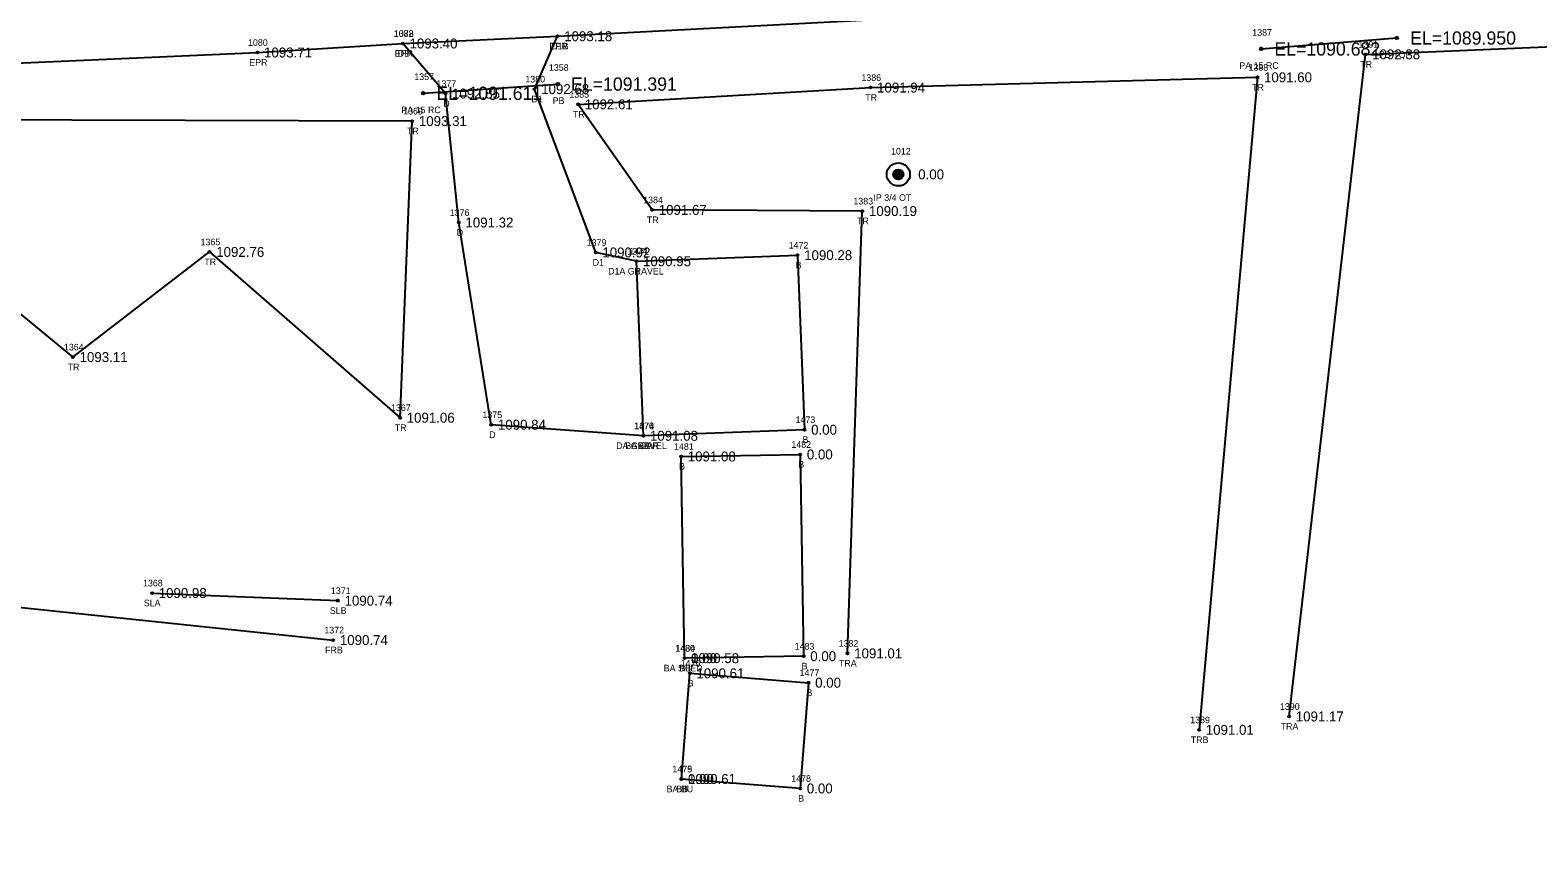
# Model space of a CAD drawing. Extents: x 1539151 to 1541799, y 1198646 to 1201165.
# Drawn here: x 1539723.1 to 1539950.8, y 1199238.5 to 1199362.5 of the extents above; entities that cross this region are included whole.
import ezdxf

# ---------------------------------------------------------------- set-up
doc = ezdxf.new("R2010")
doc.units = 0
for name, color, linetype in [('RD_EX_Bldg', 7, 'Continuous'), ('RD_EX_Bldg_txCode', 7, 'Continuous'), ('RD_EX_DR_Pipe', 7, 'Continuous'), ('RD_EX_DR_Pipe_txCode', 7, 'Continuous'), ('RD_EX_Driveway', 7, 'Continuous'), ('RD_EX_Driveway_txCode', 7, 'Continuous'), ('RD_EX_DV_Prop_txCode', 7, 'Continuous'), ('RD_EX_DV_PropPin', 7, 'Continuous'), ('RD_EX_Fence_Other', 7, 'Continuous'), ('RD_EX_Fence_Other_txCode', 7, 'Continuous'), ('RD_EX_Road', 7, 'Continuous'), ('RD_EX_Road_txCode', 7, 'Continuous'), ('RD_EX_TX_Bldg_ELEV', 7, 'Continuous'), ('RD_EX_TX_Driveway_ELEV', 7, 'Continuous'), ('RD_EX_TX_DV_Prop_ELEV', 7, 'Continuous'), ('RD_EX_TX_Fence_Other_ELEV', 7, 'Continuous'), ('RD_EX_TX_Road_ELEV', 7, 'Continuous'), ('RD_EX_TX_VEG_ELEV', 7, 'Continuous'), ('RD_EX_VEG', 7, 'Continuous'), ('RD_EX_VEG_txCode', 7, 'Continuous'), ('RD_SMD_Locator', 7, 'Continuous'), ('RD_TX_Pipe_ElevEX', 7, 'Continuous')]:
    doc.layers.add(name, color=color, linetype=linetype)

msp = doc.modelspace()

# ---------------------------------------------------------------- linework, layer by layer
at = {"layer": 'RD_EX_Bldg'}
for points in [[(1539815.75, 1199301.19), (1539814.7, 1199327.55), (1539839.04, 1199328.47), (1539840.09, 1199302.11), (1539815.75, 1199301.19)], [(1539821.96, 1199267.6), (1539821.46, 1199298.07), (1539839.45, 1199298.37), (1539839.96, 1199267.9), (1539821.96, 1199267.6)], [(1539821.49, 1199249.35), (1539822.76, 1199265.32), (1539840.7, 1199263.9), (1539839.44, 1199247.93), (1539821.49, 1199249.35)]]:
    msp.add_lwpolyline(points, dxfattribs=at)
at = {"layer": 'RD_EX_DR_Pipe'}
for p, q in [((1539909.05, 1199359.61), (1539929.55, 1199361.27)), ((1539782.5, 1199352.92), (1539802.83, 1199354.31))]:
    msp.add_line(p, q, dxfattribs=at)
at = {"layer": 'RD_EX_Driveway'}
for points in [[(1539814.7, 1199327.55), (1539808.56, 1199328.88), (1539799.32, 1199353.55), (1539802.8, 1199361.54)], [(1539815.75, 1199301.19), (1539792.79, 1199302.86), (1539787.88, 1199333.4), (1539785.86, 1199352.88), (1539779.44, 1199360.44)]]:
    msp.add_lwpolyline(points, dxfattribs=at)
at = {"layer": 'RD_EX_DV_PropPin'}
for p, q in [((1539853.52, 1199340.47), (1539853.52, 1199340.87)), ((1539853.56, 1199340.37), (1539853.56, 1199340.97)), ((1539853.59, 1199340.3), (1539853.59, 1199341.04)), ((1539853.63, 1199340.24), (1539853.63, 1199341.1)), ((1539853.66, 1199340.2), (1539853.66, 1199341.15)), ((1539853.7, 1199340.16), (1539853.7, 1199341.19)), ((1539853.73, 1199340.12), (1539853.73, 1199341.22)), ((1539853.77, 1199340.09), (1539853.77, 1199341.25)), ((1539853.8, 1199340.06), (1539853.8, 1199341.28)), ((1539853.84, 1199340.04), (1539853.84, 1199341.31)), ((1539853.87, 1199340.01), (1539853.87, 1199341.33)), ((1539853.91, 1199340), (1539853.91, 1199341.35)), ((1539853.94, 1199339.98), (1539853.94, 1199341.36)), ((1539853.98, 1199339.96), (1539853.98, 1199341.38)), ((1539854.01, 1199339.95), (1539854.01, 1199341.39)), ((1539854.05, 1199339.94), (1539854.05, 1199341.4)), ((1539854.08, 1199339.93), (1539854.08, 1199341.41)), ((1539854.12, 1199339.92), (1539854.12, 1199341.42)), ((1539854.15, 1199339.92), (1539854.15, 1199341.42)), ((1539854.19, 1199339.91), (1539854.19, 1199341.43)), ((1539854.22, 1199339.91), (1539854.22, 1199341.43)), ((1539854.26, 1199339.91), (1539854.26, 1199341.43)), ((1539854.29, 1199339.91), (1539854.29, 1199341.43)), ((1539854.33, 1199339.91), (1539854.33, 1199341.43)), ((1539854.36, 1199339.92), (1539854.36, 1199341.42)), ((1539854.4, 1199339.92), (1539854.4, 1199341.42)), ((1539854.43, 1199339.93), (1539854.43, 1199341.41)), ((1539854.47, 1199339.94), (1539854.47, 1199341.4)), ((1539854.5, 1199339.95), (1539854.5, 1199341.39)), ((1539854.54, 1199339.96), (1539854.54, 1199341.38)), ((1539854.57, 1199339.98), (1539854.57, 1199341.36)), ((1539854.61, 1199340), (1539854.61, 1199341.35)), ((1539854.64, 1199340.01), (1539854.64, 1199341.33)), ((1539854.68, 1199340.04), (1539854.68, 1199341.31)), ((1539854.71, 1199340.06), (1539854.71, 1199341.28)), ((1539854.75, 1199340.09), (1539854.75, 1199341.25)), ((1539854.78, 1199340.12), (1539854.78, 1199341.22)), ((1539854.82, 1199340.16), (1539854.82, 1199341.19)), ((1539854.85, 1199340.2), (1539854.85, 1199341.15)), ((1539854.89, 1199340.24), (1539854.89, 1199341.1)), ((1539854.92, 1199340.3), (1539854.92, 1199341.04)), ((1539854.96, 1199340.37), (1539854.96, 1199340.97)), ((1539854.99, 1199340.47), (1539854.99, 1199340.87))]:
    msp.add_line(p, q, dxfattribs=at)
for radius in [1.75, 0.761]:
    msp.add_circle((1539854.26, 1199340.67), radius, dxfattribs=at)
at = {"layer": 'RD_EX_Fence_Other'}
msp.add_line((1539711.76, 1199276.29), (1539768.92, 1199270.34), dxfattribs=at)
at = {"layer": 'RD_EX_Road'}
msp.add_lwpolyline([(1539376.14, 1199238.5), (1539389.65, 1199292.82), (1539395.62, 1199315.5), (1539405.98, 1199330.34), (1539420.48, 1199338.44), (1539434.13, 1199341.92), (1539458.27, 1199343.35), (1539505.21, 1199345.92), (1539518.44, 1199346.66), (1539558.02, 1199348.62), (1539607.46, 1199351.19), (1539654.3, 1199353.64), (1539676.57, 1199355), (1539708.42, 1199356.93), (1539757.47, 1199359.08), (1539779.44, 1199360.44), (1539802.8, 1199361.54), (1539858.43, 1199364.46), (1539908.44, 1199366.95), (1539925.86, 1199367.85), (1539963.35, 1199372.53)], dxfattribs=at)
at = {"layer": 'RD_EX_VEG'}
msp.add_line((1539741.56, 1199277.44), (1539769.63, 1199276.29), dxfattribs=at)
for points in [[(1539913.28, 1199258.8), (1539924.81, 1199358.8), (1539963.86, 1199360.44), (1540062.92, 1199384.69), (1540118.75, 1199413.61), (1540135.27, 1199341.7), (1540089.61, 1199284.74)], [(1539846.59, 1199268.33), (1539848.82, 1199335.13), (1539817.08, 1199335.31), (1539805.91, 1199351.25), (1539850.05, 1199353.78), (1539908.48, 1199355.33), (1539899.69, 1199256.78)], [(1539677.94, 1199348.99), (1539682.4, 1199334.66), (1539708.19, 1199330.64), (1539729.61, 1199313.08), (1539750.25, 1199328.96), (1539779.01, 1199303.92), (1539780.85, 1199348.72), (1539677.94, 1199348.99)]]:
    msp.add_lwpolyline(points, dxfattribs=at)
at = {"layer": 'RD_SMD_Locator'}
for centre, radius in [((1539802.8, 1199361.54), 0.15), ((1539802.8, 1199361.54), 0.15), ((1539929.55, 1199361.27), 0.2), ((1539757.47, 1199359.08), 0.15), ((1539779.44, 1199360.44), 0.15), ((1539779.44, 1199360.44), 0.15), ((1539909.05, 1199359.61), 0.2), ((1539924.81, 1199358.8), 0.15), ((1539802.83, 1199354.31), 0.2), ((1539908.48, 1199355.33), 0.15), ((1539782.5, 1199352.92), 0.2), ((1539785.86, 1199352.88), 0.15), ((1539799.32, 1199353.55), 0.15), ((1539850.05, 1199353.78), 0.15), ((1539805.91, 1199351.25), 0.15), ((1539780.85, 1199348.72), 0.15), ((1539854.26, 1199340.67), 0.15), ((1539817.08, 1199335.31), 0.15), ((1539848.82, 1199335.13), 0.15), ((1539787.88, 1199333.4), 0.15), ((1539750.25, 1199328.96), 0.15), ((1539808.56, 1199328.88), 0.15), ((1539814.7, 1199327.55), 0.15), ((1539814.7, 1199327.55), 0.15), ((1539839.04, 1199328.47), 0.15), ((1539729.61, 1199313.08), 0.15), ((1539779.01, 1199303.92), 0.15), ((1539792.79, 1199302.86), 0.15), ((1539840.09, 1199302.11), 0.15), ((1539815.75, 1199301.19), 0.15), ((1539815.75, 1199301.19), 0.15), ((1539815.75, 1199301.19), 0.15), ((1539821.46, 1199298.07), 0.15), ((1539839.45, 1199298.37), 0.15), ((1539741.56, 1199277.44), 0.15), ((1539769.63, 1199276.29), 0.15), ((1539768.92, 1199270.34), 0.15), ((1539839.96, 1199267.9), 0.15), ((1539846.59, 1199268.33), 0.15), ((1539821.96, 1199267.6), 0.15), ((1539821.96, 1199267.6), 0.15), ((1539822.76, 1199265.32), 0.15), ((1539840.7, 1199263.9), 0.15), ((1539913.28, 1199258.8), 0.15), ((1539899.69, 1199256.78), 0.15), ((1539821.49, 1199249.35), 0.15), ((1539821.49, 1199249.35), 0.15), ((1539839.44, 1199247.93), 0.15)]:
    msp.add_circle(centre, radius, dxfattribs=at)

# ---------------------------------------------------------------- texts
at = {"layer": 'RD_EX_Bldg_txCode'}
for s, p in [('1471', (1539813.64, 1199328.55)), ('1472', (1539837.7, 1199329.47)), ('B', (1539838.74, 1199326.47)), ('B', (1539814.39, 1199325.55)), ('1470', (1539814.36, 1199302.19)), ('1474', (1539814.4, 1199302.19)), ('1473', (1539838.74, 1199303.11)), ('BA GAR', (1539813.03, 1199299.19)), ('BB', (1539814.97, 1199299.19)), ('1481', (1539820.39, 1199299.07)), ('1482', (1539838.11, 1199299.37)), ('B', (1539839.78, 1199300.11)), ('B', (1539821.15, 1199296.07)), ('B', (1539839.15, 1199296.37)), ('1480', (1539820.57, 1199268.6)), ('1484', (1539820.61, 1199268.6)), ('1483', (1539838.61, 1199268.9)), ('BA SHED', (1539818.83, 1199265.6)), ('BB', (1539821.18, 1199265.6)), ('1476', (1539821.39, 1199266.32)), ('1477', (1539839.35, 1199264.9)), ('B', (1539839.65, 1199265.9)), ('B', (1539822.45, 1199263.32)), ('B', (1539840.39, 1199261.9)), ('1479', (1539820.15, 1199250.35)), ('1475', (1539820.15, 1199250.35)), ('1478', (1539838.09, 1199248.93)), ('BA BU', (1539819.26, 1199247.35)), ('BB', (1539820.71, 1199247.35)), ('B', (1539839.13, 1199245.93))]:
    msp.add_text(s, height=1, dxfattribs=at).set_placement(p)
at = {"layer": 'RD_EX_DR_Pipe_txCode'}
for s, p in [('1387', (1539907.71, 1199361.61)), ('PB TOP', (1539926.85, 1199358.27)), ('1358', (1539801.49, 1199356.31)), ('PA 15 RC', (1539905.76, 1199356.61)), ('1357', (1539781.16, 1199354.92)), ('PB', (1539802.05, 1199351.31)), ('PA 15 RC', (1539779.21, 1199349.92))]:
    msp.add_text(s, height=1, dxfattribs=at).set_placement(p)
at = {"layer": 'RD_EX_Driveway_txCode'}
for s, p in [('1378', (1539778.09, 1199361.44)), ('DB', (1539778.66, 1199358.44)), ('D1B', (1539801.86, 1199359.54)), ('1377', (1539784.51, 1199353.88)), ('1380', (1539797.93, 1199354.55)), ('D1', (1539798.85, 1199351.55)), ('D', (1539785.55, 1199350.88)), ('1376', (1539786.51, 1199334.4)), ('D', (1539787.57, 1199331.4)), ('1379', (1539807.21, 1199329.88)), ('1374', (1539813.35, 1199328.55)), ('D1', (1539808.09, 1199326.88)), ('D1A GRAVEL', (1539810.43, 1199325.55)), ('1375', (1539791.44, 1199303.86)), ('1373', (1539814.4, 1199302.19)), ('D', (1539792.48, 1199300.86)), ('DA GRAVEL', (1539811.64, 1199299.19))]:
    msp.add_text(s, height=1, dxfattribs=at).set_placement(p)
at = {"layer": 'RD_EX_DV_Prop_txCode'}
for s, p in [('1012', (1539853.16, 1199343.67)), ('IP 3/4 OT', (1539850.5, 1199336.67))]:
    msp.add_text(s, height=1, dxfattribs=at).set_placement(p)
at = {"layer": 'RD_EX_Fence_Other_txCode'}
for s, p in [('1372', (1539767.57, 1199271.34)), ('FRB', (1539767.69, 1199268.34))]:
    msp.add_text(s, height=1, dxfattribs=at).set_placement(p)
at = {"layer": 'RD_EX_Road_txCode'}
for s, p in [('1082', (1539778.06, 1199361.44)), ('1080', (1539756.05, 1199360.08)), ('EPR', (1539778.21, 1199358.44)), ('EPR', (1539801.57, 1199359.54)), ('EPR', (1539756.24, 1199357.08))]:
    msp.add_text(s, height=1, dxfattribs=at).set_placement(p)
at = {"layer": 'RD_EX_TX_Bldg_ELEV'}
for s, p in [('1090.95', (1539815.7, 1199326.8)), ('1090.28', (1539840.04, 1199327.72)), ('0.00', (1539841.09, 1199301.36)), ('1091.08', (1539816.75, 1199300.44)), ('1091.08', (1539816.75, 1199300.44)), ('1091.08', (1539822.46, 1199297.32)), ('0.00', (1539840.45, 1199297.62)), ('0.00', (1539822.96, 1199266.85)), ('1090.58', (1539822.96, 1199266.85)), ('0.00', (1539840.96, 1199267.15)), ('1090.61', (1539823.76, 1199264.57)), ('0.00', (1539841.7, 1199263.15)), ('0.00', (1539822.49, 1199248.6)), ('1090.61', (1539822.49, 1199248.6)), ('0.00', (1539840.44, 1199247.18))]:
    msp.add_text(s, height=1.5, dxfattribs=at).set_placement(p)
at = {"layer": 'RD_EX_TX_Driveway_ELEV'}
for s, p in [('1093.18', (1539803.8, 1199360.79)), ('1093.40', (1539780.44, 1199359.69)), ('1092.85', (1539786.86, 1199352.13)), ('1092.68', (1539800.32, 1199352.8)), ('1091.32', (1539788.88, 1199332.65)), ('1090.92', (1539809.56, 1199328.13)), ('1090.95', (1539815.7, 1199326.8)), ('1090.84', (1539793.79, 1199302.11)), ('1091.08', (1539816.75, 1199300.44))]:
    msp.add_text(s, height=1.5, dxfattribs=at).set_placement(p)
at = {"layer": 'RD_EX_TX_DV_Prop_ELEV'}
msp.add_text('0.00', height=1.5, dxfattribs=at).set_placement((1539857.26, 1199339.92))
at = {"layer": 'RD_EX_TX_Fence_Other_ELEV'}
msp.add_text('1090.74', height=1.5, dxfattribs=at).set_placement((1539769.92, 1199269.59))
at = {"layer": 'RD_EX_TX_Road_ELEV'}
for s, p in [('1093.18', (1539803.8, 1199360.79)), ('1093.71', (1539758.47, 1199358.33)), ('1093.40', (1539780.44, 1199359.69))]:
    msp.add_text(s, height=1.5, dxfattribs=at).set_placement(p)
at = {"layer": 'RD_EX_TX_VEG_ELEV'}
for s, p in [('1092.38', (1539925.81, 1199358.05)), ('1091.94', (1539851.05, 1199353.03)), ('1091.60', (1539909.48, 1199354.58)), ('1092.61', (1539806.91, 1199350.5)), ('1093.31', (1539781.85, 1199347.97)), ('1091.67', (1539818.08, 1199334.56)), ('1090.19', (1539849.82, 1199334.38)), ('1092.76', (1539751.25, 1199328.21)), ('1093.11', (1539730.61, 1199312.33)), ('1091.06', (1539780.01, 1199303.17)), ('1090.98', (1539742.56, 1199276.69)), ('1090.74', (1539770.63, 1199275.54)), ('1091.01', (1539847.59, 1199267.58)), ('1091.17', (1539914.28, 1199258.05)), ('1091.01', (1539900.69, 1199256.03))]:
    msp.add_text(s, height=1.5, dxfattribs=at).set_placement(p)
at = {"layer": 'RD_EX_VEG_txCode'}
for s, p in [('1391', (1539923.75, 1199359.8)), ('1388', (1539907.14, 1199356.33)), ('TR', (1539924.02, 1199356.8)), ('1386', (1539848.68, 1199354.78)), ('1385', (1539804.57, 1199352.25)), ('TR', (1539849.26, 1199351.78)), ('TR', (1539907.69, 1199353.33)), ('1369', (1539779.48, 1199349.72)), ('TR', (1539805.12, 1199349.25)), ('TR', (1539780.06, 1199346.72)), ('1384', (1539815.73, 1199336.31)), ('1383', (1539847.47, 1199336.13)), ('TR', (1539816.28, 1199333.31)), ('TR', (1539848.02, 1199333.13)), ('1365', (1539748.88, 1199329.96)), ('TR', (1539749.45, 1199326.96)), ('1364', (1539728.24, 1199314.08)), ('TR', (1539728.81, 1199311.08)), ('1367', (1539777.64, 1199304.92)), ('TR', (1539778.21, 1199301.92)), ('1368', (1539740.19, 1199278.44)), ('1371', (1539768.57, 1199277.29)), ('SLA', (1539740.31, 1199275.44)), ('SLB', (1539768.4, 1199274.29)), ('1382', (1539845.24, 1199269.33)), ('TRA', (1539845.3, 1199266.33)), ('1390', (1539911.89, 1199259.8)), ('1389', (1539898.34, 1199257.78)), ('TRA', (1539912, 1199256.8)), ('TRB', (1539898.42, 1199254.78))]:
    msp.add_text(s, height=1, dxfattribs=at).set_placement(p)
at = {"layer": 'RD_TX_Pipe_ElevEX'}
for s, p in [('EL=1089.950', (1539931.55, 1199360.27)), ('EL=1090.682', (1539911.05, 1199358.61)), ('EL=1091.391', (1539804.83, 1199353.31)), ('EL=1091.611', (1539784.5, 1199351.92))]:
    msp.add_text(s, height=2, dxfattribs=at).set_placement(p)

doc.saveas('drawing.dxf')
